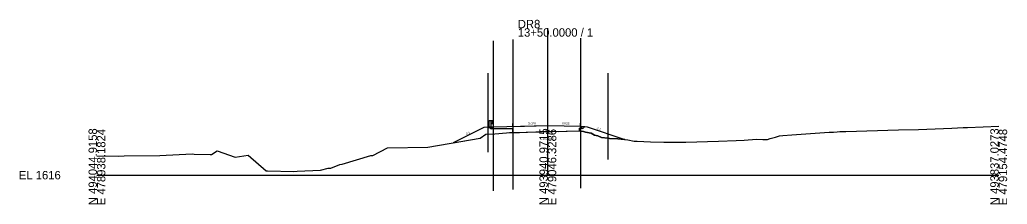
# Model space of a CAD drawing. Extents: x 24 to 353, y -10 to 3552.
# Drawn here: x 24.3 to 352.8, y 3490.3 to 3551.8 of the extents above; entities that cross this region are included whole.
import ezdxf

# ---------------------------------------------------------------- set-up
doc = ezdxf.new("R2010")
doc.units = 0
for name, color, linetype in [('Exist Cross Section Cell', 7, 'Continuous'), ('Exist XS Center Line Elevation Label', 7, 'Continuous'), ('Exist XS Ground Line', 7, 'Continuous'), ('Prop XS Dump Level', 7, 'Continuous'), ('Prop XS Earthwork Shape', 7, 'Continuous'), ('Prop XS EOT Tick Mark', 7, 'Continuous'), ('Prop XS Finish Grade', 7, 'Continuous'), ('Prop XS Finish Grade Earthwork', 7, 'Continuous'), ('Prop XS Finish Grade Pavement', 7, 'Continuous'), ('Prop XS Guardrail', 7, 'Continuous'), ('Prop XS Pvmt Edge Slope', 7, 'Continuous'), ('Prop XS SE Text', 7, 'Continuous'), ('Prop XS Shoulder Borrow Shape', 7, 'Continuous'), ('Prop XS Side Slope Text', 7, 'Continuous'), ('Prop XS Subgrade Earthwork', 7, 'Continuous'), ('Scratch_Level_1', 7, 'Continuous'), ('Scratch_Level_5', 7, 'Continuous'), ('Scratch_Level_6', 7, 'Continuous')]:
    doc.layers.add(name, color=color, linetype=linetype)

msp = doc.modelspace()

# ---------------------------------------------------------------- linework, layer by layer
at = {"layer": 'Exist Cross Section Cell'}
for p, q in [((200, 3500), (200, 3548.94)), ((50, 3500), (200, 3500)), ((200, 3500), (350, 3500))]:
    msp.add_line(p, q, dxfattribs=at)
at = {"layer": 'Exist XS Ground Line'}
msp.add_lwpolyline([(50, 3506.46), (57.07, 3506.32), (59.01, 3506.42), (70.91, 3506.52), (81.65, 3507.08), (82.3, 3507.03), (87.66, 3506.93), (88.12, 3506.91), (89.97, 3508.11), (95.95, 3506.01), (100.35, 3506.65), (106.34, 3501.49), (106.76, 3501.47), (115.51, 3501.26), (116.55, 3501.3), (124.36, 3501.7), (126.88, 3502.36), (127.82, 3502.37), (130.82, 3503.6), (131.59, 3503.66), (141.13, 3506.59), (141.83, 3506.53), (146.61, 3509.08), (160.11, 3509.36), (177.45, 3512.29), (179.38, 3513.62), (182.34, 3513.77), (186.22, 3514.1), (187.26, 3514.24), (190.57, 3514.24), (195.95, 3514.48), (199.06, 3514.63), (200, 3514.62), (203.51, 3514.59), (206.41, 3514.62), (210.48, 3514.75), (210.93, 3514.68), (211.81, 3514.5), (212.56, 3514.33), (214.4, 3513.98), (215.47, 3513.35), (216.58, 3513.06), (217.84, 3512.54), (219.98, 3512.32), (220.54, 3512.19), (223.25, 3512.16), (226.66, 3511.82), (228.67, 3511.38), (229.68, 3511.33), (234.11, 3511.1), (238.64, 3510.99), (245.91, 3511.02), (256.8, 3511.3), (262.7, 3511.5), (265.3, 3511.69), (269.42, 3512), (271.57, 3511.84), (273.11, 3511.91), (273.91, 3512.18), (275.77, 3512.7), (277.05, 3513.06), (278.15, 3513.23), (281.2, 3513.4), (293.54, 3514.28), (294.99, 3514.36), (296.3, 3514.49), (297.15, 3514.51), (299.09, 3514.54), (316.63, 3515.06), (323.29, 3515.23), (334.38, 3515.66), (338.18, 3515.86), (339.63, 3515.9), (350, 3516.31)], dxfattribs=at)
at = {"layer": 'Prop XS Dump Level'}
for p, q in [((188.39, 3516.26), (200, 3516.5)), ((200, 3516.5), (210.91, 3516.28))]:
    msp.add_line(p, q, dxfattribs=at)
at = {"layer": 'Prop XS Earthwork Shape'}
for points in [[(181.08, 3515.45), (180.45, 3516.03), (178.71, 3515.89), (168.47, 3510.78), (177.45, 3512.29), (179.38, 3513.62), (182.34, 3513.77), (186.22, 3514.1), (187.26, 3514.24), (188.39, 3514.24), (188.39, 3515.6), (181.83, 3515.47)], [(210.91, 3515.61), (211.64, 3515.6), (212.26, 3516.18), (213.05, 3516.12), (225.61, 3511.93), (223.25, 3512.16), (220.54, 3512.19), (219.98, 3512.32), (217.84, 3512.54), (216.58, 3513.06), (215.47, 3513.35), (214.4, 3513.98), (212.56, 3514.33), (211.81, 3514.5), (210.93, 3514.68), (210.48, 3514.75), (210.48, 3515.62)]]:
    msp.add_lwpolyline(points, close=True, dxfattribs=at)
at = {"layer": 'Prop XS EOT Tick Mark'}
for p, q in [((188.39, 3516.26), (188.39, 3517.26)), ((210.91, 3516.28), (210.91, 3517.28))]:
    msp.add_line(p, q, dxfattribs=at)
at = {"layer": 'Prop XS Finish Grade'}
for p, q in [((181.83, 3516.13), (180.45, 3516.03)), ((210.91, 3516.28), (212.26, 3516.18))]:
    msp.add_line(p, q, dxfattribs=at)
at = {"layer": 'Prop XS Finish Grade Earthwork'}
for p, q in [((178.72, 3515.9), (168.47, 3510.78)), ((180.45, 3516.03), (178.71, 3515.89)), ((212.26, 3516.18), (213.05, 3516.12)), ((213.05, 3516.11), (225.61, 3511.93))]:
    msp.add_line(p, q, dxfattribs=at)
at = {"layer": 'Prop XS Finish Grade Pavement'}
for p, q in [((181.83, 3516.13), (200, 3516.5)), ((200, 3516.5), (210.91, 3516.28))]:
    msp.add_line(p, q, dxfattribs=at)
at = {"layer": 'Prop XS Guardrail'}
for p, q in [((180.51, 3518.21), (181.01, 3518.21)), ((180.51, 3515.71), (180.51, 3518.21)), ((181.01, 3518.21), (181.51, 3518.21)), ((181.01, 3518.21), (181.01, 3515.71)), ((181.51, 3517.08), (181.01, 3517.08)), ((181.51, 3518.21), (181.8, 3518.01)), ((181.8, 3517.89), (181.51, 3517.69)), ((181.51, 3517.69), (181.51, 3517.6)), ((181.51, 3517.6), (181.8, 3517.4)), ((181.8, 3517.28), (181.51, 3517.08)), ((181.8, 3518.01), (181.83, 3517.95)), ((181.83, 3517.95), (181.8, 3517.89)), ((181.8, 3517.4), (181.83, 3517.34)), ((181.83, 3517.34), (181.8, 3517.28))]:
    msp.add_line(p, q, dxfattribs=at)
at = {"layer": 'Prop XS Pvmt Edge Slope'}
for p, q in [((181.83, 3516.13), (181.08, 3515.45)), ((210.91, 3516.28), (211.64, 3515.6))]:
    msp.add_line(p, q, dxfattribs=at)
at = {"layer": 'Prop XS Shoulder Borrow Shape'}
for points in [[(181.83, 3516.13), (180.45, 3516.03), (181.08, 3515.45)], [(181.83, 3516.13), (180.45, 3516.03), (181.08, 3515.45)], [(181.83, 3516.13), (180.45, 3516.03), (181.08, 3515.45)], [(210.91, 3516.28), (212.26, 3516.18), (211.64, 3515.6)], [(210.91, 3516.28), (212.26, 3516.18), (211.64, 3515.6)], [(210.91, 3516.28), (212.26, 3516.18), (211.64, 3515.6)]]:
    msp.add_lwpolyline(points, close=True, dxfattribs=at)
at = {"layer": 'Prop XS Subgrade Earthwork'}
for p, q in [((181.08, 3515.45), (180.45, 3516.03)), ((181.83, 3515.47), (181.08, 3515.45)), ((181.83, 3515.47), (188.39, 3515.6)), ((188.39, 3515.6), (188.39, 3514.24)), ((210.91, 3515.61), (210.48, 3515.62)), ((210.48, 3514.75), (210.48, 3515.62)), ((210.91, 3515.61), (211.64, 3515.6)), ((211.64, 3515.6), (212.26, 3516.18))]:
    msp.add_line(p, q, dxfattribs=at)
at = {"layer": 'Scratch_Level_1'}
for p, q in [((180, 3534), (180, 3507.63)), ((220, 3534), (220, 3505.19))]:
    msp.add_line(p, q, dxfattribs=at)
at = {"layer": 'Scratch_Level_5'}
for p, q in [((188.39, 3545.24), (188.39, 3495.24)), ((210.91, 3545.69), (210.91, 3495.69)), ((181.83, 3544.75), (181.83, 3494.75))]:
    msp.add_line(p, q, dxfattribs=at)
msp.add_lwpolyline([(50, 3506.46), (57.07, 3506.32), (59.01, 3506.42), (70.91, 3506.52), (81.65, 3507.08), (82.3, 3507.03), (87.66, 3506.93), (88.12, 3506.91), (89.97, 3508.11), (95.95, 3506.01), (100.35, 3506.65), (106.34, 3501.49), (106.76, 3501.47), (115.51, 3501.26), (116.55, 3501.3), (124.36, 3501.7), (126.88, 3502.36), (127.82, 3502.37), (130.82, 3503.6), (131.59, 3503.66), (141.13, 3506.59), (141.83, 3506.53), (146.61, 3509.08), (160.11, 3509.36), (177.45, 3512.29), (179.38, 3513.62), (182.34, 3513.77), (186.22, 3514.1), (187.26, 3514.24), (190.57, 3514.24), (195.95, 3514.48), (199.06, 3514.63), (200, 3514.62), (203.51, 3514.59), (206.41, 3514.62), (210.48, 3514.75), (210.93, 3514.68), (211.81, 3514.5), (212.56, 3514.33), (214.4, 3513.98), (215.47, 3513.35), (216.58, 3513.06), (217.84, 3512.54), (219.98, 3512.32), (220.54, 3512.19), (223.25, 3512.16), (226.66, 3511.82), (228.67, 3511.38), (229.68, 3511.33), (234.11, 3511.1), (238.64, 3510.99), (245.91, 3511.02), (256.8, 3511.3), (262.7, 3511.5), (265.3, 3511.69), (269.42, 3512), (271.57, 3511.84), (273.11, 3511.91), (273.91, 3512.18), (275.77, 3512.7), (277.05, 3513.06), (278.15, 3513.23), (281.2, 3513.4), (293.54, 3514.28), (294.99, 3514.36), (296.3, 3514.49), (297.15, 3514.51), (299.09, 3514.54), (316.63, 3515.06), (323.29, 3515.23), (334.38, 3515.66), (338.18, 3515.86), (339.63, 3515.9), (350, 3516.31)], dxfattribs=at)
at = {"layer": 'Scratch_Level_6'}
msp.add_line((188.39, 3514.24), (210.48, 3514.75), dxfattribs=at)

# ---------------------------------------------------------------- texts
at = {"layer": 'Exist Cross Section Cell'}
for s, p in [('DR8', (190, 3548.94)), ('13+50.0000 / 1', (190, 3546.14)), ('EL 1616', (24, 3498.6))]:
    msp.add_text(s, height=2.8, dxfattribs=at).set_placement(p)
for s, p in [('N 494044.9158', (50, 3490)), ('N 493940.9715', (200, 3490)), ('N 493837.0273', (350, 3490)), ('E 478938.1824', (52.8, 3490)), ('E 479046.3286', (202.8, 3490)), ('E 479154.4748', (352.8, 3490))]:
    msp.add_text(s, height=2.8, rotation=90, dxfattribs=at).set_placement(p)
at = {"layer": 'Exist XS Center Line Elevation Label'}
msp.add_text('1630.62', height=0.75, dxfattribs=at).set_placement((198.21, 3511.87))
at = {"layer": 'Prop XS Dump Level'}
for p in [(186.2, 3516.06), (213.05, 3516.08)]:
    msp.add_text('Case1', height=0.04, dxfattribs=at).set_placement(p)
at = {"layer": 'Prop XS SE Text'}
for rotation, p in [(1.1458, (193.43, 3516.85)), (358.8542, (204.65, 3516.91))]:
    msp.add_text('0.020', height=0.75, rotation=rotation, dxfattribs=at).set_placement(p)
at = {"layer": 'Prop XS Side Slope Text'}
for s, rotation, p in [('3:1', 341.5651, (216.16, 3515.35)), ('2:1', 26.5651, (172.95, 3513.29))]:
    msp.add_text(s, height=0.75, rotation=rotation, dxfattribs=at).set_placement(p)

doc.saveas('drawing.dxf')
